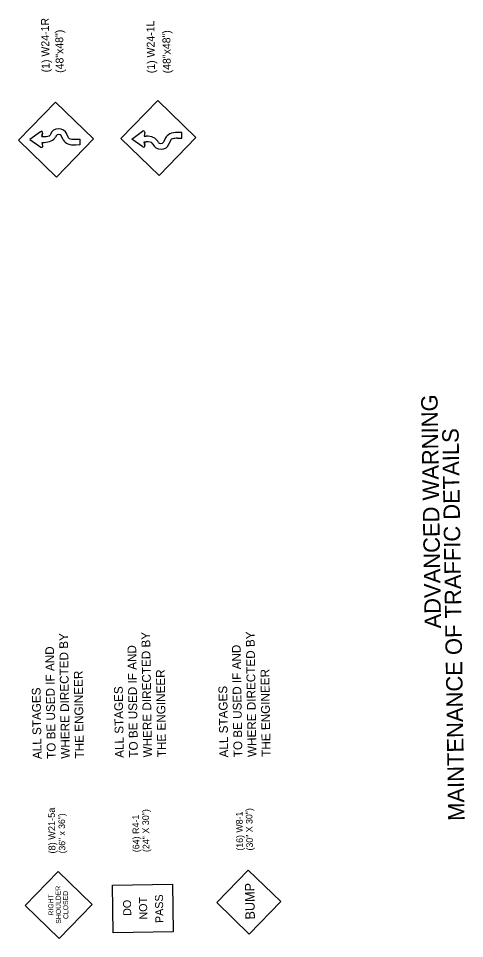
# Model space of a CAD drawing. Extents: x 1770139 to 1773492, y 718230 to 727190.
# Drawn here: x 1771600 to 1772008, y 721540 to 722381 of the extents above; entities that cross this region are included whole.
import ezdxf

# ---------------------------------------------------------------- set-up
doc = ezdxf.new("R2010")
doc.units = 0
for name, color, linetype in [('Default', 7, 'Continuous'), ('R_Dimension', 7, 'Continuous'), ('R_MOT', 7, 'Continuous')]:
    doc.layers.add(name, color=color, linetype=linetype)

msp = doc.modelspace()

# ---------------------------------------------------------------- linework, layer by layer
at = {"layer": 'R_MOT'}
for p, q in [((1771634.13, 722304.2), (1771600.36, 722269.37)), ((1771634.13, 722304.2), (1771668.97, 722270.42)), ((1771693.97, 722270.81), (1771727.75, 722305.64)), ((1771762.58, 722271.86), (1771727.75, 722305.64)), ((1771620.54, 722277.07), (1771610.7, 722269.8)), ((1771622.47, 722275.85), (1771621.86, 722272.61)), ((1771621.86, 722272.61), (1771622.47, 722275.85)), ((1771646.22, 722271.49), (1771644.28, 722275.39)), ((1771704.03, 722270.13), (1771713.8, 722277.47)), ((1771715.74, 722276.27), (1771715.14, 722273.02)), ((1771715.74, 722276.27), (1771715.14, 722273.02)), ((1771749.65, 722276.41), (1771745.5, 722276.34)), ((1771749.73, 722271.08), (1771749.65, 722276.41)), ((1771600.36, 722269.37), (1771635.19, 722235.59)), ((1771610.76, 722269.84), (1771620.75, 722262.8)), ((1771621.86, 722272.61), (1771622.96, 722272.62)), ((1771621.95, 722267.29), (1771623.77, 722267.31)), ((1771622.65, 722264.06), (1771621.95, 722267.29)), ((1771622.65, 722264.06), (1771621.95, 722267.29)), ((1771622.23, 722272.61), (1771623.68, 722272.64)), ((1771629.87, 722275.01), (1771629.29, 722273.83)), ((1771634.88, 722273.43), (1771634.3, 722272.25)), ((1771668.97, 722270.42), (1771635.19, 722235.59)), ((1771641.33, 722269.58), (1771639.39, 722273.48)), ((1771652.31, 722270.22), (1771656.47, 722270.29)), ((1771656.47, 722270.29), (1771656.55, 722264.96)), ((1771728.8, 722237.03), (1771693.97, 722270.81)), ((1771714.03, 722263.2), (1771703.97, 722270.16)), ((1771715.14, 722273.02), (1771716.95, 722273.05)), ((1771715.21, 722267.7), (1771715.92, 722264.47)), ((1771715.22, 722267.7), (1771716.31, 722267.72)), ((1771715.92, 722264.47), (1771715.22, 722267.7)), ((1771715.58, 722267.7), (1771717.03, 722267.73)), ((1771728.25, 722267.28), (1771727.64, 722268.44)), ((1771728.8, 722237.03), (1771762.58, 722271.86)), ((1771734.58, 722271.32), (1771732.76, 722267.36)), ((1771739.53, 722269.56), (1771737.71, 722265.6)), ((1771745.58, 722271.02), (1771749.73, 722271.08)), ((1771656.55, 722264.96), (1771652.4, 722264.9)), ((1771723.29, 722265.54), (1771722.68, 722266.71)), ((1771636.72, 721600.97), (1771606.55, 721569.85)), ((1771636.72, 721600.97), (1771667.82, 721570.8)), ((1771781.63, 721572.55), (1771810.36, 721602.18)), ((1771839.99, 721573.45), (1771810.36, 721602.18)), ((1771606.55, 721569.85), (1771637.67, 721539.67)), ((1771667.82, 721570.8), (1771637.67, 721539.67)), ((1771811.26, 721543.82), (1771781.63, 721572.55)), ((1771811.26, 721543.82), (1771839.99, 721573.45))]:
    msp.add_line(p, q, dxfattribs=at)
msp.add_lwpolyline([(1771686.17, 721588.53), (1771741.1, 721589.37), (1771741.77, 721545.79), (1771686.84, 721544.94)], close=True, dxfattribs=at)
for centre, start, end in [((1771621.27, 722276.08), 349.35257, 126.44422), ((1771714.54, 722276.49), 349.38698, 126.9301), ((1771621.45, 722263.8), 234.83528, 12.3784), ((1771714.72, 722264.21), 235.32116, 12.41281)]:
    msp.add_arc(centre, 1.23, start, end, dxfattribs=at)
for centre, major_axis, ratio, start_param, end_param in [((1771637.13, 722273.05), (-7.68, -0.12), 0.87995, 3.425387, 5.985653), ((1771745.27, 722269.6), (11.1, 0.17), 0.608565, 1.512481, 2.857799), ((1771623.66, 722274.07), (5.78, 0.09), 0.247932, 4.712389, 6.055172), ((1771623.66, 722274.07), (11.1, 0.17), 0.608565, 4.712389, 5.985355), ((1771637.13, 722273.05), (-2.35, -0.04), 0.608565, 3.425387, 5.985653), ((1771651.96, 722271.64), (11.1, 0.17), 0.608565, 3.425387, 4.770704), ((1771651.96, 722271.64), (5.78, 0.09), 0.247932, 3.179688, 4.770704), ((1771717.06, 722266.3), (11.1, 0.17), 0.608565, 0.297831, 1.570796), ((1771717.06, 722266.3), (5.78, 0.09), 0.247932, 0.228014, 1.570796), ((1771730.49, 722267.73), (-2.35, -0.04), 0.608565, 0.297533, 2.857799), ((1771745.27, 722269.6), (5.78, 0.09), 0.247932, 1.512481, 3.103497), ((1771730.49, 722267.73), (-7.68, -0.12), 0.87995, 0.297533, 2.857799)]:
    msp.add_ellipse(centre, major_axis=major_axis, ratio=ratio, start_param=start_param, end_param=end_param, dxfattribs=at)

# ---------------------------------------------------------------- texts
at = {"layer": 'Default'}
for s, p in [('ADVANCED WARNING ', (1771986.49, 721823.16)), ('MAINTENANCE OF TRAFFIC DETAILS', (1772007.98, 721647.37))]:
    msp.add_text(s, height=15, rotation=90.88269, dxfattribs=at).set_placement(p)
at = {"layer": 'R_Dimension'}
for s, p in [('WHERE DIRECTED BY', (1771647.33, 721704.15)), ('WHERE DIRECTED BY', (1771722.4, 721705.31)), ('WHERE DIRECTED BY', (1771817.83, 721705.68)), ('TO BE USED IF AND', (1771634.45, 721703.96)), ('TO BE USED IF AND', (1771709.53, 721705.11)), ('TO BE USED IF AND', (1771804.95, 721705.48)), ('THE ENGINEER', (1771660.2, 721704.35)), ('THE ENGINEER', (1771735.28, 721705.51)), ('THE ENGINEER', (1771830.7, 721705.88)), ('ALL STAGES', (1771621.58, 721703.76)), ('ALL STAGES', (1771696.65, 721704.91)), ('ALL STAGES', (1771792.07, 721705.28))]:
    msp.add_text(s, height=8, rotation=90.88269, dxfattribs=at).set_placement(p)
at = {"layer": 'R_MOT'}
for s, height, rotation, p in [('(1) W24-1R', 7.195, 90.88269, (1771628.88, 722331.33)), ('(1) W24-1L', 7.195, 90.88269, (1771725.21, 722330.52)), ('(48"x48")', 7.194, 90.88269, (1771641.71, 722330.87)), ('(48"x48")', 7.194, 90.88269, (1771739.64, 722330.43)), ('(8) W21-5a', 6.273, 90.88269, (1771634.26, 721617.45)), ('(36" x 36")', 5.88, 90.88269, (1771643.28, 721617.59)), ('(24" X 30")', 6.084, 90.88269, (1771720.09, 721618.78)), ('(16) W8-1', 6.002, 90.88269, (1771805.62, 721620.09)), ('(30" X 30")', 6.0016, 90.88269, (1771814.62, 721620.23)), ('(64) R4-1', 6.084, 90.88269, (1771710.96, 721618.64)), ('SHOULDER', 4.515, 90.88272, (1771639.28, 721553.32)), ('BUMP', 8.642, 90.88269, (1771816.41, 721557.17)), ('RIGHT', 4.516, 90.88314, (1771632.39, 721560.83)), ('CLOSED', 4.516, 90.88326, (1771645.99, 721557.6)), ('NOT', 7.312, 90.88269, (1771718.11, 721557.14)), ('PASS', 7.312, 90.88269, (1771732.79, 721553.97)), ('DO', 7.312, 90.88269, (1771703.43, 721560.49))]:
    msp.add_text(s, height=height, rotation=rotation, dxfattribs=at).set_placement(p)

doc.saveas('drawing.dxf')
